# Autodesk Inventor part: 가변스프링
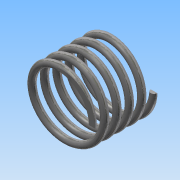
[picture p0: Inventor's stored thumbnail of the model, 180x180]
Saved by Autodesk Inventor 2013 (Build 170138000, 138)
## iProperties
Created: 2019-01
Part Number: 가변스프링
Material: 스테인리스강
Document SubType Name: Modeling
Designer: Administrator
Mass: 7.81385 g
Surface Area: 19.6267 cm^2
Volume: 0.967061 cm^3
Density: 8.08 g/cm^3
Author: Administrator
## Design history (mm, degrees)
sketch "스케치1"
  geometry: L1 (0, 0)-(10, 0); L2 (10, 0)-(10, 18.7); L3 (10, 18.7)-(0, 18.7); L4 (0, 18.7)-(0, 0); C1 r 1 at (10, 0)
  constraints: 8 end point, 2 parallel, 1 centre point, 1 coincident, 1 horizontal, 1 perpendicular
  dimensions: "d0" = 2 diameter of C1; "d1" = 20 diameter of L2 L4; "d2" = 18.7 distance of L1.end L2.end (derived)
feature "코일1" sketch "스케치1" pitch "d3" = 10; turns "d5" = 5; dims "d4" = 18.7 (= d2), "d6" = 0, angle "d7" = 90 deg, angle "d8" = 90 deg, "d9" = 0, "d10" = 0
sketch "스케치2"
  geometry: L1 (-9, 0)-(-11, 0) reference; 1 further point
  constraints: 1 horizontal alignment
extrude "돌출1" cut sketch "스케치2" stored distance "d11" = 10; taper "d12" = 0 deg
node "작업 평면1"
sketch "스케치3"
  geometry: L1 (-11, 0)-(-9, 0) reference; 1 further point
  constraints: 1 horizontal alignment
extrude "돌출2" cut sketch "스케치3" stored distance "d14" = 10; taper "d15" = 0 deg
node "솔리드1"
node "절단 모서리 투영1"
node "절단 모서리 투영2"
other parameters: "d13" = 18.7 (= d2)
